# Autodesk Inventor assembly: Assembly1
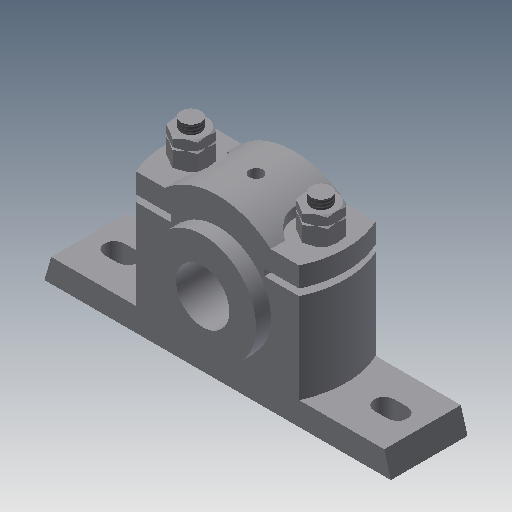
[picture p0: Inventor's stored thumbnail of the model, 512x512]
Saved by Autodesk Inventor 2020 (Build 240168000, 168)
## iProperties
Created: 2015-03
Part Number: Assembly1
Document SubType Name: Assembly
Designer: Sandeep
Author: Sandeep
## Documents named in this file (7)
- D:\Autodesk Inventor_2020\Resources\Resources\Inventor_2020_tut\Inventor_2020_tut\c11_Inv_2020_tut\c11_Inv_tut_2020\c11_tut02_inv\Plummer Block.iam
- D:\Autodesk Inventor_2020\Resources\Resources\Inventor_2020_tut\Inventor_2020_tut\c11_Inv_2020_tut\c11_Inv_tut_2020\c11_tut02_inv\Casting.ipt
- D:\Autodesk Inventor_2020\Resources\Resources\Inventor_2020_tut\Inventor_2020_tut\c11_Inv_2020_tut\c11_Inv_tut_2020\c11_tut02_inv\Brasses.ipt
- D:\Autodesk Inventor_2020\Resources\Resources\Inventor_2020_tut\Inventor_2020_tut\c11_Inv_2020_tut\c11_Inv_tut_2020\c11_tut02_inv\Cap.ipt
- D:\Autodesk Inventor_2020\Resources\Resources\Inventor_2020_tut\Inventor_2020_tut\c11_Inv_2020_tut\c11_Inv_tut_2020\c11_tut02_inv\Bolt.ipt
- D:\Autodesk Inventor_2020\Resources\Resources\Inventor_2020_tut\Inventor_2020_tut\c11_Inv_2020_tut\c11_Inv_tut_2020\c11_tut02_inv\Nut.ipt
- D:\Autodesk Inventor_2020\Resources\Resources\Inventor_2020_tut\Inventor_2020_tut\c11_Inv_2020_tut\c11_Inv_tut_2020\c11_tut02_inv\locknut.ipt
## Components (9 placed, 6 different names)
1. Casting:1 — Mate:1, Mate:2, Insert:1, Insert:2, Angle:1, Angle:2
2. Brasses:1 — Mate:1, Mate:2, Mate:3, Mate:4
3. Cap:1 — Mate:3, Mate:4, Insert:3, Insert:4
4. Bolt:1 — Insert:1, Angle:2
5. Bolt:2 — Insert:2, Angle:1
6. Nut:1 — Insert:3, Insert:5
7. Nut:2 — Insert:4, Insert:6
8. locknut:1 — Insert:5
9. locknut:2 — Insert:6
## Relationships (12: Insert 6, Mate 4, Angle 2)
- Mate:1: Casting:1 ↔ Brasses:1
- Mate:2: Casting:1 ↔ Brasses:1
- Mate:3: Brasses:1 ↔ Cap:1
- Mate:4: Brasses:1 ↔ Cap:1
- Insert:1: Casting:1 ↔ Bolt:1
- Insert:2: Casting:1 ↔ Bolt:2
- Angle:1: Casting:1 ↔ Bolt:2
- Angle:2: Casting:1 ↔ Bolt:1
- Insert:3: Cap:1 ↔ Nut:1
- Insert:4: Cap:1 ↔ Nut:2
- Insert:5: Nut:1 ↔ locknut:1
- Insert:6: Nut:2 ↔ locknut:2
